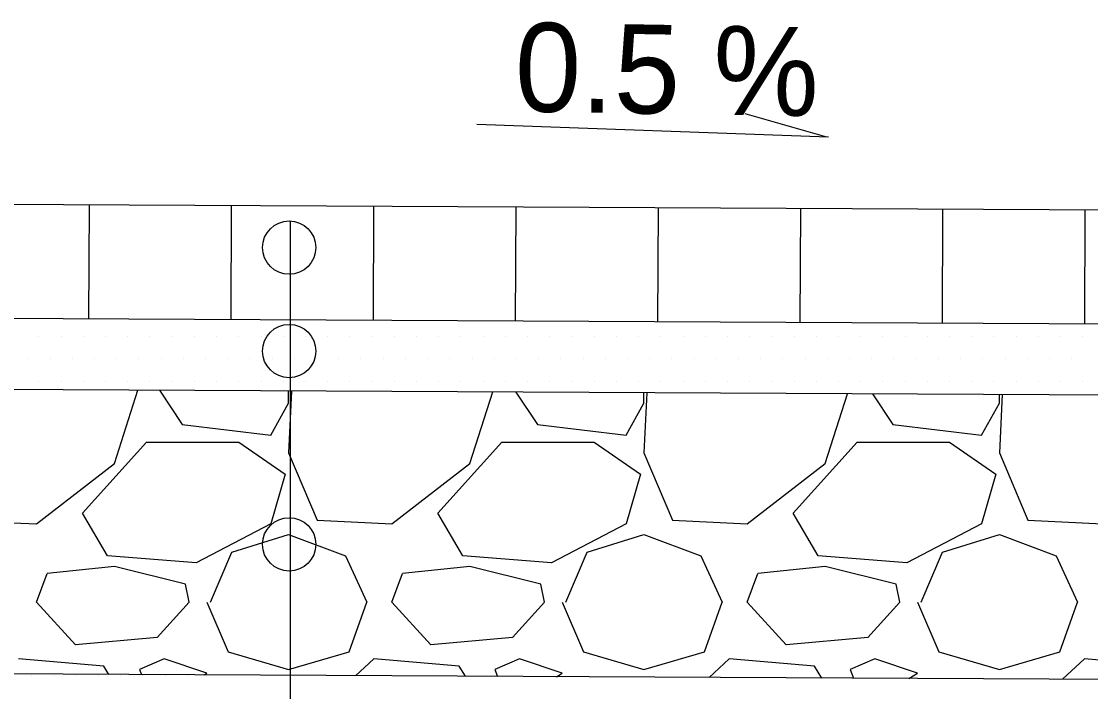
# Model space of a CAD drawing. Extents: x -219625893 to 7498339, y 5791790 to 5792761.
# Drawn here: x 7495265.29 to 7495280.34, y 5791866.01 to 5791875.44 of the extents above; entities that cross this region are included whole.
import ezdxf

# ---------------------------------------------------------------- set-up
doc = ezdxf.new("R2010")
doc.units = 0
for name, color, linetype in [('D_kons_wyp_podsypka_cem-piask', 7, 'Continuous'), ('D_kons_wyp_pospolka', 7, 'Continuous'), ('D_robocze_1', 7, 'Continuous'), ('Level 10', 7, 'Continuous'), ('wymiary', 7, 'Continuous')]:
    doc.layers.add(name, color=color, linetype=linetype)

msp = doc.modelspace()

# ---------------------------------------------------------------- linework, layer by layer
at = {"layer": 'D_kons_wyp_podsypka_cem-piask'}
for p, q in [((7495265.539, 5791871.005), (7495265.539, 5791871.005)), ((7495265.852, 5791871.005), (7495265.852, 5791871.005)), ((7495266.164, 5791871.005), (7495266.164, 5791871.005)), ((7495266.477, 5791871.005), (7495266.477, 5791871.005)), ((7495266.789, 5791871.005), (7495266.789, 5791871.005)), ((7495267.102, 5791871.005), (7495267.102, 5791871.005)), ((7495267.414, 5791871.005), (7495267.414, 5791871.005)), ((7495267.727, 5791871.005), (7495267.727, 5791871.005)), ((7495268.039, 5791871.005), (7495268.039, 5791871.005)), ((7495268.352, 5791871.005), (7495268.352, 5791871.005)), ((7495268.664, 5791871.005), (7495268.664, 5791871.005)), ((7495268.977, 5791871.005), (7495268.977, 5791871.005)), ((7495269.289, 5791871.005), (7495269.289, 5791871.005)), ((7495269.602, 5791871.005), (7495269.602, 5791871.005)), ((7495269.914, 5791871.005), (7495269.914, 5791871.005)), ((7495270.227, 5791871.005), (7495270.227, 5791871.005)), ((7495270.539, 5791871.005), (7495270.539, 5791871.005)), ((7495270.852, 5791871.005), (7495270.852, 5791871.005)), ((7495271.164, 5791871.005), (7495271.164, 5791871.005)), ((7495271.477, 5791871.005), (7495271.477, 5791871.005)), ((7495271.789, 5791871.005), (7495271.789, 5791871.005)), ((7495272.102, 5791871.005), (7495272.102, 5791871.005)), ((7495272.414, 5791871.005), (7495272.414, 5791871.005)), ((7495272.727, 5791871.005), (7495272.727, 5791871.005)), ((7495273.039, 5791871.005), (7495273.039, 5791871.005)), ((7495273.352, 5791871.005), (7495273.352, 5791871.005)), ((7495273.664, 5791871.005), (7495273.664, 5791871.005)), ((7495273.977, 5791871.005), (7495273.977, 5791871.005)), ((7495274.289, 5791871.005), (7495274.289, 5791871.005)), ((7495274.602, 5791871.005), (7495274.602, 5791871.005)), ((7495274.914, 5791871.005), (7495274.914, 5791871.005)), ((7495275.227, 5791871.005), (7495275.227, 5791871.005)), ((7495275.539, 5791871.005), (7495275.539, 5791871.005)), ((7495275.852, 5791871.005), (7495275.852, 5791871.005)), ((7495276.164, 5791871.005), (7495276.164, 5791871.005)), ((7495276.477, 5791871.005), (7495276.477, 5791871.005)), ((7495276.789, 5791871.005), (7495276.789, 5791871.005)), ((7495277.102, 5791871.005), (7495277.102, 5791871.005)), ((7495277.414, 5791871.005), (7495277.414, 5791871.005)), ((7495277.727, 5791871.005), (7495277.727, 5791871.005)), ((7495278.039, 5791871.005), (7495278.039, 5791871.005)), ((7495278.352, 5791871.005), (7495278.352, 5791871.005)), ((7495278.664, 5791871.005), (7495278.664, 5791871.005)), ((7495278.977, 5791871.005), (7495278.977, 5791871.005)), ((7495279.289, 5791871.005), (7495279.289, 5791871.005)), ((7495279.602, 5791871.005), (7495279.602, 5791871.005)), ((7495279.914, 5791871.005), (7495279.914, 5791871.005)), ((7495280.227, 5791871.005), (7495280.227, 5791871.005)), ((7495265.383, 5791870.693), (7495265.383, 5791870.693)), ((7495265.695, 5791870.693), (7495265.695, 5791870.693)), ((7495266.008, 5791870.693), (7495266.008, 5791870.693)), ((7495266.32, 5791870.693), (7495266.32, 5791870.693)), ((7495266.633, 5791870.693), (7495266.633, 5791870.693)), ((7495266.945, 5791870.693), (7495266.945, 5791870.693)), ((7495267.258, 5791870.693), (7495267.258, 5791870.693)), ((7495267.57, 5791870.693), (7495267.57, 5791870.693)), ((7495267.883, 5791870.693), (7495267.883, 5791870.693)), ((7495268.195, 5791870.693), (7495268.195, 5791870.693)), ((7495268.508, 5791870.693), (7495268.508, 5791870.693)), ((7495268.82, 5791870.693), (7495268.82, 5791870.693)), ((7495269.133, 5791870.693), (7495269.133, 5791870.693)), ((7495269.445, 5791870.693), (7495269.445, 5791870.693)), ((7495269.758, 5791870.693), (7495269.758, 5791870.693)), ((7495270.07, 5791870.693), (7495270.07, 5791870.693)), ((7495270.383, 5791870.693), (7495270.383, 5791870.693)), ((7495270.695, 5791870.693), (7495270.695, 5791870.693)), ((7495271.008, 5791870.693), (7495271.008, 5791870.693)), ((7495271.32, 5791870.693), (7495271.32, 5791870.693)), ((7495271.633, 5791870.693), (7495271.633, 5791870.693)), ((7495271.945, 5791870.693), (7495271.945, 5791870.693)), ((7495272.258, 5791870.693), (7495272.258, 5791870.693)), ((7495272.57, 5791870.693), (7495272.57, 5791870.693)), ((7495272.883, 5791870.693), (7495272.883, 5791870.693)), ((7495273.195, 5791870.693), (7495273.195, 5791870.693)), ((7495273.508, 5791870.693), (7495273.508, 5791870.693)), ((7495273.82, 5791870.693), (7495273.82, 5791870.693)), ((7495274.133, 5791870.693), (7495274.133, 5791870.693)), ((7495274.445, 5791870.693), (7495274.445, 5791870.693)), ((7495274.758, 5791870.693), (7495274.758, 5791870.693)), ((7495275.07, 5791870.693), (7495275.07, 5791870.693)), ((7495275.383, 5791870.693), (7495275.383, 5791870.693)), ((7495275.695, 5791870.693), (7495275.695, 5791870.693)), ((7495276.008, 5791870.693), (7495276.008, 5791870.693)), ((7495276.32, 5791870.693), (7495276.32, 5791870.693)), ((7495276.633, 5791870.693), (7495276.633, 5791870.693)), ((7495276.945, 5791870.693), (7495276.945, 5791870.693)), ((7495277.258, 5791870.693), (7495277.258, 5791870.693)), ((7495277.57, 5791870.693), (7495277.57, 5791870.693)), ((7495277.883, 5791870.693), (7495277.883, 5791870.693)), ((7495278.195, 5791870.693), (7495278.195, 5791870.693)), ((7495278.508, 5791870.693), (7495278.508, 5791870.693)), ((7495278.82, 5791870.693), (7495278.82, 5791870.693)), ((7495279.133, 5791870.693), (7495279.133, 5791870.693)), ((7495279.445, 5791870.693), (7495279.445, 5791870.693)), ((7495279.758, 5791870.693), (7495279.758, 5791870.693)), ((7495280.07, 5791870.693), (7495280.07, 5791870.693)), ((7495265.539, 5791870.38), (7495265.539, 5791870.38)), ((7495265.852, 5791870.38), (7495265.852, 5791870.38)), ((7495266.164, 5791870.38), (7495266.164, 5791870.38)), ((7495266.477, 5791870.38), (7495266.477, 5791870.38)), ((7495266.789, 5791870.38), (7495266.789, 5791870.38)), ((7495267.102, 5791870.38), (7495267.102, 5791870.38)), ((7495267.414, 5791870.38), (7495267.414, 5791870.38)), ((7495267.727, 5791870.38), (7495267.727, 5791870.38)), ((7495268.039, 5791870.38), (7495268.039, 5791870.38)), ((7495268.352, 5791870.38), (7495268.352, 5791870.38)), ((7495268.664, 5791870.38), (7495268.664, 5791870.38)), ((7495268.977, 5791870.38), (7495268.977, 5791870.38)), ((7495269.289, 5791870.38), (7495269.289, 5791870.38)), ((7495269.602, 5791870.38), (7495269.602, 5791870.38)), ((7495269.914, 5791870.38), (7495269.914, 5791870.38)), ((7495270.227, 5791870.38), (7495270.227, 5791870.38)), ((7495270.539, 5791870.38), (7495270.539, 5791870.38)), ((7495270.852, 5791870.38), (7495270.852, 5791870.38)), ((7495271.164, 5791870.38), (7495271.164, 5791870.38)), ((7495271.477, 5791870.38), (7495271.477, 5791870.38)), ((7495271.789, 5791870.38), (7495271.789, 5791870.38)), ((7495272.102, 5791870.38), (7495272.102, 5791870.38)), ((7495272.414, 5791870.38), (7495272.414, 5791870.38)), ((7495272.727, 5791870.38), (7495272.727, 5791870.38)), ((7495273.039, 5791870.38), (7495273.039, 5791870.38)), ((7495273.352, 5791870.38), (7495273.352, 5791870.38)), ((7495273.664, 5791870.38), (7495273.664, 5791870.38)), ((7495273.977, 5791870.38), (7495273.977, 5791870.38)), ((7495274.289, 5791870.38), (7495274.289, 5791870.38)), ((7495274.602, 5791870.38), (7495274.602, 5791870.38)), ((7495274.914, 5791870.38), (7495274.914, 5791870.38)), ((7495275.227, 5791870.38), (7495275.227, 5791870.38)), ((7495275.539, 5791870.38), (7495275.539, 5791870.38)), ((7495275.852, 5791870.38), (7495275.852, 5791870.38)), ((7495276.164, 5791870.38), (7495276.164, 5791870.38)), ((7495276.477, 5791870.38), (7495276.477, 5791870.38)), ((7495276.789, 5791870.38), (7495276.789, 5791870.38)), ((7495277.102, 5791870.38), (7495277.102, 5791870.38)), ((7495277.414, 5791870.38), (7495277.414, 5791870.38)), ((7495277.727, 5791870.38), (7495277.727, 5791870.38)), ((7495278.039, 5791870.38), (7495278.039, 5791870.38)), ((7495278.352, 5791870.38), (7495278.352, 5791870.38)), ((7495278.664, 5791870.38), (7495278.664, 5791870.38)), ((7495278.977, 5791870.38), (7495278.977, 5791870.38)), ((7495279.289, 5791870.38), (7495279.289, 5791870.38)), ((7495279.602, 5791870.38), (7495279.602, 5791870.38)), ((7495279.914, 5791870.38), (7495279.914, 5791870.38)), ((7495280.227, 5791870.38), (7495280.227, 5791870.38))]:
    msp.add_line(p, q, dxfattribs=at)
at = {"layer": 'D_kons_wyp_pospolka'}
for p, q in [((7495266.603, 5791869.222), (7495266.932, 5791870.252)), ((7495267.234, 5791870.251), (7495267.553, 5791869.772)), ((7495269.053, 5791870.072), (7495269.053, 5791870.241)), ((7495269.094, 5791870.241), (7495269.053, 5791869.372)), ((7495271.603, 5791869.222), (7495271.925, 5791870.227)), ((7495272.251, 5791870.225), (7495272.553, 5791869.772)), ((7495274.053, 5791870.072), (7495274.053, 5791870.216)), ((7495274.093, 5791870.216), (7495274.053, 5791869.372)), ((7495268.803, 5791869.622), (7495269.053, 5791870.072)), ((7495273.803, 5791869.622), (7495274.053, 5791870.072)), ((7495276.603, 5791869.222), (7495276.917, 5791870.202)), ((7495277.267, 5791870.2), (7495277.553, 5791869.772)), ((7495278.803, 5791869.622), (7495279.053, 5791870.072)), ((7495279.053, 5791870.072), (7495279.053, 5791870.191)), ((7495279.092, 5791870.191), (7495279.053, 5791869.372)), ((7495267.553, 5791869.772), (7495268.803, 5791869.622)), ((7495272.553, 5791869.772), (7495273.803, 5791869.622)), ((7495277.553, 5791869.772), (7495278.803, 5791869.622)), ((7495266.153, 5791868.522), (7495267.053, 5791869.522)), ((7495267.053, 5791869.522), (7495268.353, 5791869.522)), ((7495268.353, 5791869.522), (7495269.003, 5791869.072)), ((7495271.153, 5791868.522), (7495272.053, 5791869.522)), ((7495272.053, 5791869.522), (7495273.353, 5791869.522)), ((7495273.353, 5791869.522), (7495274.003, 5791869.072)), ((7495276.153, 5791868.522), (7495277.053, 5791869.522)), ((7495277.053, 5791869.522), (7495278.353, 5791869.522)), ((7495278.353, 5791869.522), (7495279.003, 5791869.072)), ((7495269.053, 5791869.372), (7495269.453, 5791868.422)), ((7495274.053, 5791869.372), (7495274.453, 5791868.422)), ((7495279.053, 5791869.372), (7495279.453, 5791868.422)), ((7495265.503, 5791868.373), (7495266.603, 5791869.223)), ((7495270.503, 5791868.373), (7495271.603, 5791869.223)), ((7495275.503, 5791868.372), (7495276.603, 5791869.222)), ((7495269.003, 5791869.072), (7495268.803, 5791868.372)), ((7495274.003, 5791869.072), (7495273.803, 5791868.372)), ((7495279.003, 5791869.072), (7495278.803, 5791868.372)), ((7495264.453, 5791868.422), (7495265.503, 5791868.372)), ((7495266.503, 5791867.922), (7495266.153, 5791868.522)), ((7495269.453, 5791868.422), (7495270.503, 5791868.372)), ((7495271.503, 5791867.922), (7495271.153, 5791868.522)), ((7495274.453, 5791868.422), (7495275.503, 5791868.372)), ((7495276.503, 5791867.922), (7495276.153, 5791868.522)), ((7495279.453, 5791868.422), (7495280.503, 5791868.372)), ((7495268.803, 5791868.372), (7495267.753, 5791867.822)), ((7495273.803, 5791868.372), (7495272.753, 5791867.822)), ((7495278.803, 5791868.372), (7495277.753, 5791867.822)), ((7495268.253, 5791867.972), (7495269.053, 5791868.222)), ((7495269.053, 5791868.222), (7495269.853, 5791867.922)), ((7495273.253, 5791867.972), (7495274.053, 5791868.222)), ((7495274.053, 5791868.222), (7495274.853, 5791867.922)), ((7495278.253, 5791867.972), (7495279.053, 5791868.222)), ((7495279.053, 5791868.222), (7495279.853, 5791867.922)), ((7495267.953, 5791867.272), (7495268.253, 5791867.972)), ((7495272.953, 5791867.272), (7495273.253, 5791867.972)), ((7495277.953, 5791867.272), (7495278.253, 5791867.972)), ((7495267.753, 5791867.822), (7495266.503, 5791867.922)), ((7495269.853, 5791867.922), (7495270.153, 5791867.272)), ((7495272.753, 5791867.822), (7495271.503, 5791867.922)), ((7495274.853, 5791867.922), (7495275.153, 5791867.272)), ((7495277.753, 5791867.822), (7495276.503, 5791867.922)), ((7495279.853, 5791867.922), (7495280.153, 5791867.272)), ((7495265.503, 5791867.272), (7495265.653, 5791867.672)), ((7495266.603, 5791867.772), (7495265.653, 5791867.672)), ((7495267.603, 5791867.522), (7495266.603, 5791867.772)), ((7495270.503, 5791867.272), (7495270.653, 5791867.672)), ((7495271.603, 5791867.772), (7495270.653, 5791867.672)), ((7495272.603, 5791867.522), (7495271.603, 5791867.772)), ((7495275.503, 5791867.272), (7495275.653, 5791867.672)), ((7495276.603, 5791867.772), (7495275.653, 5791867.672)), ((7495277.603, 5791867.522), (7495276.603, 5791867.772)), ((7495267.653, 5791867.272), (7495267.603, 5791867.522)), ((7495272.653, 5791867.272), (7495272.603, 5791867.522)), ((7495277.653, 5791867.272), (7495277.603, 5791867.522)), ((7495266.053, 5791866.672), (7495265.503, 5791867.272)), ((7495267.653, 5791867.272), (7495267.203, 5791866.772)), ((7495267.903, 5791867.272), (7495268.203, 5791866.572)), ((7495269.903, 5791866.572), (7495270.153, 5791867.272)), ((7495271.053, 5791866.672), (7495270.503, 5791867.272)), ((7495272.653, 5791867.272), (7495272.203, 5791866.772)), ((7495272.903, 5791867.272), (7495273.203, 5791866.572)), ((7495274.903, 5791866.572), (7495275.153, 5791867.272)), ((7495276.053, 5791866.672), (7495275.503, 5791867.272)), ((7495277.653, 5791867.272), (7495277.203, 5791866.772)), ((7495277.903, 5791867.272), (7495278.203, 5791866.572)), ((7495279.903, 5791866.572), (7495280.153, 5791867.272)), ((7495267.203, 5791866.772), (7495266.053, 5791866.672)), ((7495272.203, 5791866.772), (7495271.053, 5791866.672)), ((7495277.203, 5791866.772), (7495276.053, 5791866.672)), ((7495266.453, 5791866.372), (7495265.253, 5791866.472)), ((7495267.303, 5791866.472), (7495266.953, 5791866.322)), ((7495267.903, 5791866.272), (7495267.303, 5791866.472)), ((7495268.203, 5791866.572), (7495269.053, 5791866.322)), ((7495269.053, 5791866.322), (7495269.903, 5791866.572)), ((7495270.253, 5791866.472), (7495269.995, 5791866.237)), ((7495271.453, 5791866.372), (7495270.253, 5791866.472)), ((7495272.303, 5791866.472), (7495271.953, 5791866.322)), ((7495272.903, 5791866.272), (7495272.303, 5791866.472)), ((7495273.203, 5791866.572), (7495274.053, 5791866.322)), ((7495274.053, 5791866.322), (7495274.903, 5791866.572)), ((7495275.253, 5791866.472), (7495274.968, 5791866.212)), ((7495276.453, 5791866.372), (7495275.253, 5791866.472)), ((7495277.303, 5791866.472), (7495276.953, 5791866.322)), ((7495277.903, 5791866.272), (7495277.303, 5791866.472)), ((7495278.203, 5791866.572), (7495279.053, 5791866.322)), ((7495279.053, 5791866.322), (7495279.903, 5791866.572)), ((7495280.253, 5791866.472), (7495279.941, 5791866.187)), ((7495281.453, 5791866.372), (7495280.253, 5791866.472)), ((7495266.525, 5791866.254), (7495266.453, 5791866.372)), ((7495266.953, 5791866.322), (7495266.981, 5791866.252)), ((7495271.54, 5791866.229), (7495271.453, 5791866.372)), ((7495271.953, 5791866.322), (7495271.991, 5791866.227)), ((7495276.555, 5791866.204), (7495276.453, 5791866.372)), ((7495276.953, 5791866.322), (7495277.001, 5791866.202)), ((7495265.439, 5791866.244), (7495265.439, 5791866.244)), ((7495265.752, 5791866.244), (7495265.752, 5791866.244)), ((7495266.064, 5791866.244), (7495266.064, 5791866.244)), ((7495266.377, 5791866.244), (7495266.377, 5791866.244)), ((7495266.689, 5791866.244), (7495266.689, 5791866.244)), ((7495267.002, 5791866.244), (7495267.002, 5791866.244)), ((7495267.314, 5791866.244), (7495267.314, 5791866.244)), ((7495267.627, 5791866.244), (7495267.627, 5791866.244)), ((7495267.862, 5791866.247), (7495267.903, 5791866.272)), ((7495267.939, 5791866.244), (7495267.939, 5791866.244)), ((7495268.252, 5791866.244), (7495268.252, 5791866.244)), ((7495272.82, 5791866.223), (7495272.903, 5791866.272)), ((7495277.779, 5791866.198), (7495277.903, 5791866.272))]:
    msp.add_line(p, q, dxfattribs=at)
at = {"layer": 'D_robocze_1'}
msp.add_line((7495269.072, 5791872.633), (7495269.072, 5791837.19), dxfattribs=at)
at = {"layer": 'Level 10'}
for p, q in [((7495298.458, 5791872.694), (7495250.391, 5791872.935)), ((7495266.241, 5791871.256), (7495266.249, 5791872.855)), ((7495268.243, 5791871.246), (7495268.251, 5791872.845)), ((7495270.245, 5791871.235), (7495270.253, 5791872.835)), ((7495272.247, 5791871.225), (7495272.255, 5791872.825)), ((7495274.249, 5791871.215), (7495274.257, 5791872.815)), ((7495276.25, 5791871.205), (7495276.258, 5791872.805)), ((7495278.252, 5791871.195), (7495278.26, 5791872.795)), ((7495280.254, 5791871.185), (7495280.262, 5791872.785)), ((7495298.461, 5791871.094), (7495250.391, 5791871.335))]:
    msp.add_line(p, q, dxfattribs=at)
at = {"layer": 'wymiary'}
for p, q in [((7495276.624, 5791873.812), (7495275.475, 5791874.141)), ((7495276.649, 5791873.811), (7495271.701, 5791873.991)), ((7495298.462, 5791870.094), (7495250.386, 5791870.335)), ((7495298.468, 5791866.094), (7495250.366, 5791866.335))]:
    msp.add_line(p, q, dxfattribs=at)
for centre in [(7495269.061, 5791872.258), (7495269.061, 5791870.803), (7495269.061, 5791868.084)]:
    msp.add_circle(centre, 0.375, dxfattribs=at)

# ---------------------------------------------------------------- texts
msp.add_text('0.5 %', height=1.2509, rotation=359.0545, dxfattribs=at).set_placement((7495272.228, 5791874.175))

doc.saveas('drawing.dxf')
